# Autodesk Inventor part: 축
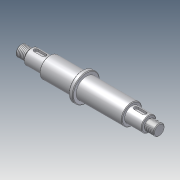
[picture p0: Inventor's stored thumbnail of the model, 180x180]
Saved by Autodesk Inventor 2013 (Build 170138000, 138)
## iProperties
Company: 한국ATC센터
Created: 2015-02
Part Number: 축
Document SubType Name: Modeling
Designer: KYOUNG IL JANG
Density: 1 g/cm^3
Material: 일반
Author: KYOUNG IL JANG
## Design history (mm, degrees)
sketch "스케치1"
  geometry: L1 (0, 0)-(203, 0); L2 (203, 0)-(203, 8); L3 (203, 8)-(189.5, 8); L4 (189.5, 8)-(189.5, 7); L5 (189.5, 7)-(188, 7); L6 (188, 7)-(188, 11); L7 (188, 11)-(163, 11); L8 (163, 11)-(163, 15); L9 (163, 15)-(96, 15); L10 (96, 15)-(96, 20); L11 (96, 20)-(90, 20); L12 (90, 20)-(90, 15); L13 (90, 15)-(42, 15); L14 (42, 15)-(42, 11); L15 (42, 11)-(15, 11); L16 (15, 11)-(15, 7); L17 (15, 7)-(13.5, 7); L18 (0, 8)-(0, 0); L19 (0, 8)-(13.5, 8); L20 (13.5, 8)-(13.5, 7)
  constraints: 40 end point, 16 parallel, 3 perpendicular, 1 collinear, 1 horizontal
  dimensions: "d0" = 16 diameter of L3 L1; "d1" = 14 diameter of L5 L1; "d2" = 22 diameter of L7 L1; "d3" = 30 diameter of L9 L1; "d4" = 40 diameter of L11 L1; "d5" = 16 diameter of L19 L1; "d6" = 22 diameter of L15 L1; "d8" = 1.5 distance of L16.end L17.end; "d9" = 15 distance between parallel lines of L16 L18; "d10" = 27 distance between parallel lines of L14 L16; "d11" = 48 distance between parallel lines of L12 L14; "d15" = 203 distance of L1.start L1.end; "d16" = 1.5 distance of L4.end L5.end; "d17" = 14 diameter of L17 L1; "d36" = 15 distance between parallel lines of L6 L2; "d37" = 25 distance between parallel lines of L6 L8; "d38" = 6 distance between parallel lines of L10 L12
revolve "회전1" sketch "스케치1" stored, may be unused: angle "d18" = 90 deg
feature "스레드1" dims "d19" = 10, "d20" = 0
feature "스레드2" dims "d21" = 10, "d22" = 0
chamfer "모따기1" distance "d23" = 1; stored, may be unused: second distance "d24" = 2, angle "d25" = 45 deg
node "작업 평면1"
sketch "스케치2"
  geometry: L1 (-6.5, 3)-(5.5, 3); L2 (5.5, -3)-(-6.5, -3); L3 (-13.5, -10)-(-13.5, 10) reference; L4 (140.5, 3)-(152.5, 3); L5 (152.5, -3)-(140.5, -3); L6 (159.5, 10)-(159.5, -10) reference; A1 r 3 centre (5.5, 0) between (5.5, -3) and (5.5, 3); A2 r 3 centre (-6.5, 0) between (-6.5, 3) and (-6.5, -3); A3 r 3 centre (152.5, 0) between (152.5, -3) and (152.5, 3); A4 r 3 centre (140.5, 0) between (140.5, 3) and (140.5, -3); 1 further point
  constraints: 8 end point, 8 point on circle, 8 tangent, 4 centre point, 2 horizontal, 2 horizontal alignment, 2 parallel
  dimensions: "d26" = 6 distance between parallel lines of L2 L1; "d27" = 18 dimension on A1 A2; "d28" = 4 distance edge to line of A2 L3; "d29" = 6 distance between parallel lines of L5 L4; "d30" = 18 dimension on A3 A4; "d31" = 4 distance edge to line of A3 L6
extrude "돌출1" cut sketch "스케치2" distance "d32" = 3.5; taper "d33" = 0 deg
node "솔리드1"
